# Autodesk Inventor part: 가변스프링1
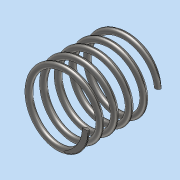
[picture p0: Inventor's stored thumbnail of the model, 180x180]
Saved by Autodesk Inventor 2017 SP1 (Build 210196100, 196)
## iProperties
Part Number: 가변스프링1
Material: 강철, 연강
Document SubType Name: Modeling
Designer: MRC
Density: 7.85 g/cm^3
Appearance: 반연마
Mass: 8.38159 g
Surface Area: 21.6554 cm^2
Volume: 1.06772 cm^3
Author: MRC
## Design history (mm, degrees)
sketch "스케치1"
  geometry: L1 (0, 0)-(0, 25.358); L2 (0, 25.358)-(11, 25.358); L3 (0, 0)-(11, 0); C1 r 1 at (11, 0)
  constraints: 6 end point, 2 horizontal, 1 centre point, 1 coincident, 1 vertical
  dimensions: "d0" = 25.35829 distance of L1.start L1.end (derived); "d1" = 11 distance of L1.end L2.end; "d2" = 22 diameter of L3.end L1; "d3" = 2 diameter of C1
feature "코일1" sketch "스케치1" pitch "d4" = 10; turns "d6" = 5; dims "d5" = 25.35829 (= d0), "d7" = 0, angle "d8" = 90 deg, angle "d9" = 90 deg, "d10" = 0, "d11" = 0
sketch "스케치2"
  geometry: L1 (25.358, 20)-(0, 20); L2 (0, 20)-(0, -20); L3 (0, -20)-(25.358, -20); L4 (25.358, -20)-(25.358, 20); 2 further points
  constraints: 8 end point, 2 parallel, 1 coincident, 1 horizontal, 1 midpoint, 1 perpendicular
  dimensions: "d12" = 25.35829 distance of L2.end L3.end (= d0); "d13" = 40 distance of L3.end L1.start
extrude "돌출1" sketch "스케치2" stored distance "d14" = 0; taper "d15" = 0 deg
node "솔리드1"
